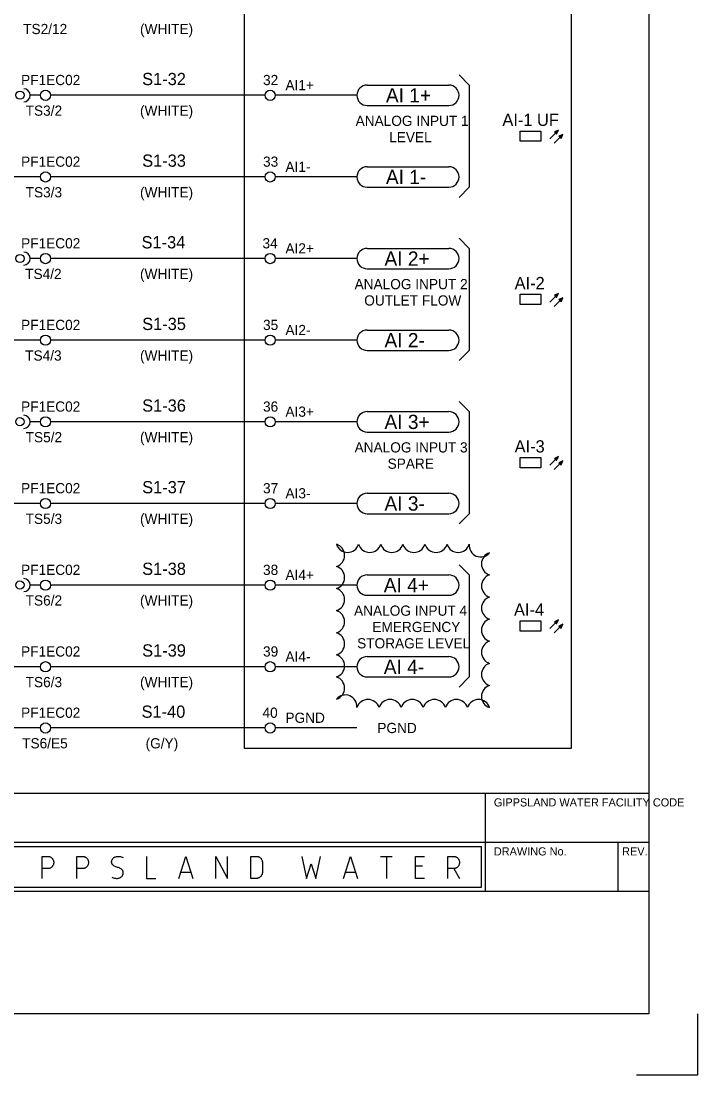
# Model space of a CAD drawing. Extents: x 0 to 841, y 0 to 594.
# Drawn here: x 675.3 to 841, y 0 to 258.2 of the extents above; entities that cross this region are included whole.
import ezdxf

# ---------------------------------------------------------------- set-up
doc = ezdxf.new("R2010")
doc.units = 0
for name, color, linetype in [('A1BORDER', 7, 'Continuous'), ('Level 1', 7, 'Continuous'), ('Level 10', 7, 'Continuous')]:
    doc.layers.add(name, color=color, linetype=linetype)

msp = doc.modelspace()

# ---------------------------------------------------------------- linework, layer by layer
at = {"layer": 'A1BORDER'}
for p, q in [((829, 581), (829, 15)), ((592.5, 69), (829, 69)), ((789, 45), (789, 69)), ((28, 57), (829, 57)), ((821.5, 45), (821.5, 57)), ((637, 56), (788, 56)), ((788, 46), (788, 56)), ((663, 46), (788, 46)), ((664, 45), (829, 45)), ((829, 15), (28, 15)), ((829, 15), (829, 15)), ((841, 0), (841, 15)), ((826, 0), (841, 0))]:
    msp.add_line(p, q, dxfattribs=at)
for points in [[(680.42, 48.16), (680.42, 53.54), (681.84, 53.54), (681.96, 53.54), (682.08, 53.52), (682.2, 53.49), (682.32, 53.45), (682.43, 53.4), (682.54, 53.34), (682.65, 53.27), (682.74, 53.19), (682.84, 53.1), (682.92, 53), (682.99, 52.9), (683.06, 52.79), (683.12, 52.67), (683.17, 52.56), (683.21, 52.43), (683.23, 52.31), (683.25, 52.18), (683.26, 52.05), (683.25, 51.91), (683.23, 51.78), (683.21, 51.66), (683.17, 51.53), (683.12, 51.42), (683.06, 51.3), (682.99, 51.19), (682.92, 51.09), (682.84, 50.99), (682.74, 50.9), (682.65, 50.82), (682.54, 50.75), (682.43, 50.69), (682.32, 50.64), (682.2, 50.6), (682.08, 50.57), (681.96, 50.55), (681.84, 50.55), (680.42, 50.55)], [(688.93, 48.16), (688.93, 53.54), (690.35, 53.54), (690.47, 53.54), (690.59, 53.52), (690.71, 53.49), (690.83, 53.45), (690.94, 53.4), (691.05, 53.34), (691.16, 53.27), (691.26, 53.19), (691.35, 53.1), (691.43, 53), (691.51, 52.9), (691.57, 52.79), (691.63, 52.67), (691.68, 52.56), (691.72, 52.43), (691.75, 52.31), (691.76, 52.18), (691.77, 52.05), (691.76, 51.91), (691.75, 51.78), (691.72, 51.66), (691.68, 51.53), (691.63, 51.42), (691.57, 51.3), (691.51, 51.19), (691.43, 51.09), (691.35, 50.99), (691.26, 50.9), (691.16, 50.82), (691.05, 50.75), (690.94, 50.69), (690.83, 50.64), (690.71, 50.6), (690.59, 50.57), (690.47, 50.55), (690.35, 50.55), (688.93, 50.55)], [(697.45, 48.46), (697.67, 48.36), (697.9, 48.27), (698.12, 48.21), (698.36, 48.17), (698.6, 48.16), (698.84, 48.16), (698.87, 48.16), (699.03, 48.18), (699.18, 48.21), (699.33, 48.26), (699.48, 48.32), (699.62, 48.4), (699.72, 48.46), (699.81, 48.53), (699.9, 48.61), (699.98, 48.69), (700.05, 48.78), (700.11, 48.88), (700.17, 48.99), (700.22, 49.09), (700.25, 49.21), (700.28, 49.32), (700.29, 49.36), (700.3, 49.44), (700.3, 49.52), (700.3, 49.61), (700.29, 49.69), (700.27, 49.77), (700.25, 49.86), (700.22, 49.93), (700.18, 50.01), (700.14, 50.09), (700.09, 50.15), (700.04, 50.21), (700.01, 50.25), (699.85, 50.39), (699.69, 50.51), (699.52, 50.61), (699.34, 50.7), (699.15, 50.78), (698.95, 50.83), (698.87, 50.85), (698.68, 50.9), (698.49, 50.96), (698.3, 51.04), (698.12, 51.14), (697.96, 51.26), (697.8, 51.39), (697.73, 51.45), (697.67, 51.51), (697.62, 51.57), (697.58, 51.64), (697.53, 51.71), (697.5, 51.79), (697.47, 51.87), (697.46, 51.95), (697.44, 52.04), (697.43, 52.12), (697.43, 52.21), (697.44, 52.29), (697.45, 52.35), (697.47, 52.46), (697.51, 52.58), (697.55, 52.69), (697.61, 52.79), (697.67, 52.89), (697.74, 52.99), (697.82, 53.07), (697.9, 53.15), (697.99, 53.23), (698.02, 53.24), (698.15, 53.33), (698.3, 53.4), (698.44, 53.45), (698.6, 53.5), (698.75, 53.52), (698.87, 53.54), (699.11, 53.55), (699.35, 53.53), (699.58, 53.49), (699.82, 53.43), (700.04, 53.35), (700.27, 53.25)], [(705.96, 53.54), (705.96, 48.16), (708.23, 48.16)], [(713.91, 48.16), (715.61, 53.54), (717.32, 48.16)], [(722.99, 48.16), (722.99, 53.54), (725.83, 48.16), (725.83, 53.54)], [(731.52, 48.16), (731.52, 53.54), (732.94, 53.54), (733.06, 53.54), (733.18, 53.52), (733.3, 53.49), (733.42, 53.45), (733.53, 53.4), (733.64, 53.34), (733.75, 53.27), (733.84, 53.19), (733.94, 53.1), (734.02, 53), (734.09, 52.9), (734.16, 52.79), (734.22, 52.67), (734.27, 52.56), (734.31, 52.43), (734.33, 52.31), (734.35, 52.18), (734.36, 52.05), (734.36, 49.66), (734.35, 49.52), (734.33, 49.39), (734.31, 49.27), (734.27, 49.14), (734.22, 49.02), (734.16, 48.91), (734.09, 48.8), (734.02, 48.7), (733.94, 48.6), (733.84, 48.51), (733.75, 48.43), (733.64, 48.36), (733.53, 48.3), (733.42, 48.25), (733.3, 48.21), (733.18, 48.18), (733.06, 48.16), (732.94, 48.16), (731.52, 48.16)], [(744.01, 53.54), (745.14, 48.16), (746.28, 51.75), (747.41, 48.16), (748.55, 53.54)], [(754.22, 48.16), (755.92, 53.54), (757.63, 48.16)], [(763.31, 53.54), (766.15, 53.54)], [(764.73, 53.54), (764.73, 48.16)], [(774.09, 48.16), (771.82, 48.16), (771.82, 53.54), (774.09, 53.54)], [(779.78, 48.16), (779.78, 53.54), (781.2, 53.54), (781.32, 53.54), (781.44, 53.52), (781.56, 53.49), (781.68, 53.45), (781.79, 53.4), (781.9, 53.34), (782.01, 53.27), (782.1, 53.19), (782.2, 53.1), (782.28, 53), (782.35, 52.9), (782.42, 52.79), (782.48, 52.67), (782.53, 52.56), (782.56, 52.43), (782.59, 52.31), (782.61, 52.18), (782.61, 52.05), (782.61, 51.91), (782.59, 51.78), (782.56, 51.66), (782.53, 51.53), (782.48, 51.42), (782.42, 51.3), (782.35, 51.19), (782.28, 51.09), (782.2, 50.99), (782.1, 50.9), (782.01, 50.82), (781.9, 50.75), (781.79, 50.69), (781.68, 50.64), (781.56, 50.6), (781.44, 50.57), (781.32, 50.55), (781.2, 50.55), (779.78, 50.55)], [(714.48, 49.66), (716.75, 49.66)], [(754.79, 49.66), (757.06, 49.66)], [(773.53, 51.15), (771.82, 51.15)], [(781.2, 50.55), (782.61, 48.16)]]:
    msp.add_lwpolyline(points, dxfattribs=at)
at = {"layer": 'Level 1'}
for p, q in [((760, 242.5), (780, 242.5)), ((680, 240), (677.5, 240)), ((735, 240), (682.5, 240)), ((757.5, 240), (737.5, 240)), ((760, 237.5), (780, 237.5)), ((760, 222.5), (780, 222.5)), ((680, 220), (600, 220)), ((735, 220), (682.5, 220)), ((757.5, 220), (737.5, 220)), ((760, 217.5), (780, 217.5)), ((760, 202.5), (780, 202.5)), ((680, 200), (677.5, 200)), ((735, 200), (682.5, 200)), ((757.5, 200), (737.5, 200)), ((760, 197.5), (780, 197.5)), ((760, 182.5), (780, 182.5)), ((680, 180), (600, 180)), ((735, 180), (682.5, 180)), ((757.5, 180), (737.5, 180)), ((760, 177.5), (780, 177.5)), ((760, 162.5), (780, 162.5)), ((680, 160), (677.5, 160)), ((735, 160), (682.5, 160)), ((757.5, 160), (737.5, 160)), ((760, 157.5), (780, 157.5)), ((760, 142.5), (780, 142.5)), ((680, 140), (632.5, 140)), ((735, 140), (682.5, 140)), ((757.5, 140), (737.5, 140)), ((760, 137.5), (780, 137.5)), ((760, 122.5), (780, 122.5)), ((680, 120), (677.5, 120)), ((735, 120), (682.5, 120)), ((757.5, 120), (737.5, 120)), ((760, 117.5), (780, 117.5)), ((760, 102.5), (780, 102.5)), ((680, 100), (540, 100)), ((735, 100), (682.5, 100)), ((757.5, 100), (737.5, 100)), ((760, 97.5), (780, 97.5)), ((680, 85), (670, 85)), ((735, 85), (682.5, 85)), ((757.5, 85), (737.5, 85))]:
    msp.add_line(p, q, dxfattribs=at)
for points in [[(810, 556.45), (810, 80), (730, 80), (730, 548.55)], [(782.5, 245), (785, 242.5), (785, 217.5), (782.5, 215)], [(782.5, 205), (785, 202.5), (785, 177.5), (782.5, 175)], [(782.5, 165), (785, 162.5), (785, 137.5), (782.5, 135)], [(782.5, 125), (785, 122.5), (785, 97.5), (782.5, 95)]]:
    msp.add_lwpolyline(points, dxfattribs=at)
for points in [[(797.5, 231.25), (802.5, 231.25), (802.5, 228.75), (797.5, 228.75)], [(797.5, 191.25), (802.5, 191.25), (802.5, 188.75), (797.5, 188.75)], [(797.5, 151.25), (802.5, 151.25), (802.5, 148.75), (797.5, 148.75)], [(797.5, 111.25), (802.5, 111.25), (802.5, 108.75), (797.5, 108.75)]]:
    msp.add_lwpolyline(points, close=True, dxfattribs=at)
for centre in [(674.98, 240.03), (674.98, 200.03), (674.98, 160.03), (674.98, 120.03)]:
    msp.add_circle(centre, 1, dxfattribs=at)
for centre, radius, start, end in [((760, 240), 2.5, 90, 270), ((780, 240), 2.5, 270, 90), ((760, 220), 2.5, 90, 270), ((780, 220), 2.5, 270, 90), ((760, 200), 2.5, 90, 270), ((780, 200), 2.5, 270, 90), ((760, 180), 2.5, 90, 270), ((780, 180), 2.5, 270, 90), ((760, 160), 2.5, 90, 270), ((780, 160), 2.5, 270, 90), ((760, 140), 2.5, 90, 270), ((780, 140), 2.5, 270, 90), ((755.21, 130.85), 2.84, 197.5, 342.5), ((751.65, 127.29), 2.84, 287.5, 72.5), ((760.63, 130.85), 2.84, 197.5, 342.5), ((766.04, 130.85), 2.84, 197.5, 342.5), ((771.46, 130.85), 2.84, 197.5, 342.5), ((776.88, 130.85), 2.84, 197.5, 342.5), ((782.29, 130.85), 2.84, 197.5, 342.5), ((787.83, 129.75), 2.84, 174.9059, 319.9059), ((790.85, 125.21), 2.84, 107.5, 252.5), ((751.65, 121.87), 2.84, 287.5, 72.5), ((760, 120), 2.5, 90, 270), ((780, 120), 2.5, 270, 90), ((790.85, 119.79), 2.84, 107.5, 252.5), ((751.65, 116.46), 2.84, 287.5, 72.5), ((790.85, 114.38), 2.84, 107.5, 252.5), ((751.65, 111.04), 2.84, 287.5, 72.5), ((790.85, 108.96), 2.84, 107.5, 252.5), ((751.65, 105.62), 2.84, 287.5, 72.5), ((790.85, 103.54), 2.84, 107.5, 252.5), ((751.65, 100.21), 2.84, 287.5, 72.5), ((760, 100), 2.5, 90, 270), ((780, 100), 2.5, 270, 90), ((790.85, 98.13), 2.84, 107.5, 252.5), ((751.65, 94.79), 2.84, 287.5, 72.5), ((754.67, 90.25), 2.84, 354.9059, 139.9059), ((790.85, 92.71), 2.84, 107.5, 252.5), ((760.21, 89.15), 2.84, 17.5, 162.5), ((765.62, 89.15), 2.84, 17.5, 162.5), ((771.04, 89.15), 2.84, 17.5, 162.5), ((776.46, 89.15), 2.84, 17.5, 162.5), ((781.87, 89.15), 2.84, 17.5, 162.5), ((787.29, 89.15), 2.84, 17.5, 162.5)]:
    msp.add_arc(centre, radius, start, end, dxfattribs=at)
at = {"layer": 'Level 10'}
for p, q in [((804.73, 229.35), (806.86, 231.48)), ((805.79, 228.29), (807.91, 230.42)), ((805.96, 231.07), (806.67, 231.07)), ((806, 230.92), (806.61, 230.92)), ((806.14, 230.77), (806.53, 230.77)), ((806.29, 231.22), (806.74, 231.22)), ((806.3, 230.62), (806.47, 230.62)), ((806.62, 231.37), (806.81, 231.37)), ((807.02, 230.01), (807.73, 230.01)), ((807.06, 229.86), (807.66, 229.86)), ((807.35, 230.16), (807.8, 230.16)), ((807.68, 230.31), (807.87, 230.31)), ((807.21, 229.71), (807.6, 229.71)), ((807.36, 229.56), (807.53, 229.56)), ((804.73, 189.35), (806.86, 191.48)), ((805.96, 191.07), (806.67, 191.07)), ((806.29, 191.22), (806.74, 191.22)), ((806.62, 191.37), (806.81, 191.37)), ((805.79, 188.29), (807.91, 190.42)), ((806, 190.92), (806.61, 190.92)), ((806.14, 190.77), (806.53, 190.77)), ((806.3, 190.62), (806.47, 190.62)), ((807.02, 190.01), (807.73, 190.01)), ((807.06, 189.86), (807.66, 189.86)), ((807.21, 189.71), (807.6, 189.71)), ((807.35, 190.16), (807.8, 190.16)), ((807.36, 189.56), (807.53, 189.56)), ((807.68, 190.31), (807.87, 190.31)), ((804.73, 149.35), (806.86, 151.48)), ((805.79, 148.29), (807.91, 150.42)), ((805.96, 151.07), (806.67, 151.07)), ((806, 150.92), (806.61, 150.92)), ((806.14, 150.77), (806.53, 150.77)), ((806.29, 151.22), (806.74, 151.22)), ((806.3, 150.62), (806.47, 150.62)), ((806.62, 151.37), (806.81, 151.37)), ((807.02, 150.01), (807.73, 150.01)), ((807.06, 149.86), (807.66, 149.86)), ((807.35, 150.16), (807.8, 150.16)), ((807.68, 150.31), (807.87, 150.31)), ((807.21, 149.71), (807.6, 149.71)), ((807.36, 149.56), (807.53, 149.56)), ((804.73, 109.35), (806.86, 111.48)), ((805.96, 111.07), (806.67, 111.07)), ((806.29, 111.22), (806.74, 111.22)), ((806.62, 111.37), (806.81, 111.37)), ((805.79, 108.29), (807.91, 110.42)), ((806, 110.92), (806.61, 110.92)), ((806.14, 110.77), (806.53, 110.77)), ((806.3, 110.62), (806.47, 110.62)), ((807.02, 110.01), (807.73, 110.01)), ((807.06, 109.86), (807.66, 109.86)), ((807.21, 109.71), (807.6, 109.71)), ((807.35, 110.16), (807.8, 110.16)), ((807.36, 109.56), (807.53, 109.56)), ((807.68, 110.31), (807.87, 110.31))]:
    msp.add_line(p, q, dxfattribs=at)
for points in [[(806.86, 231.48), (805.88, 231.04), (806.41, 230.5)], [(807.91, 230.42), (806.94, 229.98), (807.48, 229.44)], [(806.86, 191.48), (805.88, 191.04), (806.41, 190.5)], [(807.91, 190.42), (806.94, 189.98), (807.48, 189.44)], [(806.86, 151.48), (805.88, 151.04), (806.41, 150.5)], [(807.91, 150.42), (806.94, 149.98), (807.48, 149.44)], [(806.86, 111.48), (805.88, 111.04), (806.41, 110.5)], [(807.91, 110.42), (806.94, 109.98), (807.48, 109.44)]]:
    msp.add_lwpolyline(points, close=True, dxfattribs=at)
for centre in [(681.25, 240), (736.25, 240), (681.25, 220), (736.25, 220), (681.25, 200), (736.25, 200), (681.25, 180), (736.25, 180), (681.25, 160), (736.25, 160), (681.25, 140), (736.25, 140), (681.25, 120), (736.25, 120), (681.25, 100), (736.25, 100), (681.25, 85), (736.25, 85)]:
    msp.add_circle(centre, 1.25, dxfattribs=at)
for centre in [(675.9, 240), (675.9, 200), (675.9, 160), (675.9, 120)]:
    msp.add_arc(centre, 1.6, 270, 90, dxfattribs=at)

# ---------------------------------------------------------------- texts
at = {"layer": 'A1BORDER'}
for s, p in [('GIPPSLAND WATER FACILITY CODE', (791.03, 65.77)), ('DRAWING No.', (791.03, 53.77)), ('REV.', (822.43, 53.77))]:
    msp.add_text(s, height=2, dxfattribs=at).set_placement(p)
at = {"layer": 'Level 1'}
for s, height, p in [('TS2/12', 2.5, (675.78, 255)), ('(WHITE)', 2.5, (704.39, 255)), ('S1-32', 3, (704.92, 242.5)), ('PF1EC02', 2.5, (675.27, 242.5)), ('32', 2.5, (734.51, 242.5)), ('AI1+', 2.5, (740, 241.25)), ('AI 1+', 3.5, (764.6, 238.25)), ('TS3/2', 2.5, (676.39, 235)), ('(WHITE)', 2.5, (704.39, 235)), ('ANALOG INPUT 1', 2.5, (757.18, 232.5)), ('AI-1 UF', 3, (793.13, 232.5)), ('LEVEL', 2.5, (765.39, 228.5)), ('PF1EC02', 2.5, (675.27, 222.5)), ('S1-33', 3, (704.92, 222.5)), ('33', 2.5, (734.51, 222.5)), ('AI1-', 2.5, (740, 221.25)), ('AI 1-', 3.5, (764.6, 218.25)), ('TS3/3', 2.5, (676.39, 215)), ('(WHITE)', 2.5, (704.39, 215)), ('PF1EC02', 2.5, (675.27, 202.5)), ('S1-34', 3, (704.77, 202.5)), ('34', 2.5, (734.38, 202.5)), ('AI2+', 2.5, (740, 201.25)), ('AI 2+', 3.5, (764.25, 198.25)), ('TS4/2', 2.5, (676.27, 195)), ('(WHITE)', 2.5, (704.39, 195)), ('ANALOG INPUT 2', 2.5, (756.93, 192.5)), ('AI-2', 3, (796.12, 192.5)), ('OUTLET FLOW', 2.5, (759.29, 188.5)), ('PF1EC02', 2.5, (675.27, 182.5)), ('S1-35', 3, (704.92, 182.5)), ('35', 2.5, (734.51, 182.5)), ('AI2-', 2.5, (740, 181.25)), ('AI 2-', 3.5, (764.25, 178.25)), ('TS4/3', 2.5, (676.27, 175)), ('(WHITE)', 2.5, (704.39, 175)), ('S1-36', 3, (704.92, 162.5)), ('PF1EC02', 2.5, (675.27, 162.5)), ('36', 2.5, (734.51, 162.5)), ('AI3+', 2.5, (740, 161.25)), ('AI 3+', 3.5, (764.25, 158.25)), ('TS5/2', 2.5, (676.39, 155)), ('(WHITE)', 2.5, (704.39, 155)), ('ANALOG INPUT 3', 2.5, (756.93, 152.5)), ('AI-3', 3, (796.12, 152.5)), ('SPARE', 2.5, (765.02, 148.5)), ('PF1EC02', 2.5, (675.27, 142.5)), ('S1-37', 3, (704.92, 142.5)), ('37', 2.5, (734.51, 142.5)), ('AI3-', 2.5, (740, 141.25)), ('AI 3-', 3.5, (764.25, 138.25)), ('TS5/3', 2.5, (676.39, 135)), ('(WHITE)', 2.5, (704.39, 135)), ('PF1EC02', 2.5, (675.27, 122.5)), ('S1-38', 3, (704.92, 122.5)), ('38', 2.5, (734.51, 122.5)), ('AI4+', 2.5, (740, 121.25)), ('AI 4+', 3.5, (764.08, 118.25)), ('TS6/2', 2.5, (676.39, 115)), ('(WHITE)', 2.5, (704.39, 115)), ('ANALOG INPUT 4', 2.5, (756.8, 112.5)), ('AI-4', 3, (795.97, 112.5)), ('EMERGENCY', 2.5, (761.28, 108.5)), ('STORAGE LEVEL', 2.5, (757.55, 104.5)), ('PF1EC02', 2.5, (675.27, 102.5)), ('S1-39', 3, (704.92, 102.5)), ('39', 2.5, (734.51, 102.5)), ('AI4-', 2.5, (740, 101.25)), ('AI 4-', 3.5, (764.08, 98.25)), ('TS6/3', 2.5, (676.39, 95)), ('(WHITE)', 2.5, (704.39, 95)), ('S1-40', 3, (704.77, 87.5)), ('PF1EC02', 2.5, (675.27, 87.5)), ('40', 2.5, (734.38, 87.5)), ('PGND', 2.5, (740, 86.25)), ('PGND', 2.5, (762.5, 83.75)), ('TS6/E5', 2.5, (675.53, 80)), ('(G/Y)', 2.5, (705.76, 80))]:
    msp.add_text(s, height=height, dxfattribs=at).set_placement(p)

doc.saveas('drawing.dxf')
